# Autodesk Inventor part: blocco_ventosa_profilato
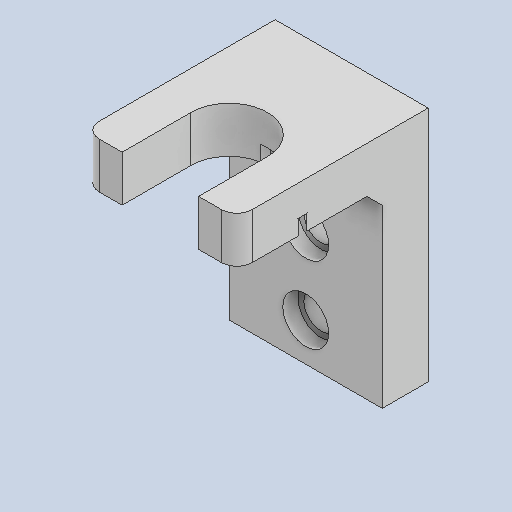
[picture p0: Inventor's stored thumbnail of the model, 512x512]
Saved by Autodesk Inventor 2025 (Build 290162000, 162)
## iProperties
Created: 2026-03
Part Number: blocco_ventosa_profilato
Material: Generico
Document SubType Name: Modeling
Designer: Ryzen5700u
Density: 1 g/cm^3
Appearance: Default
Author: Ryzen5700u
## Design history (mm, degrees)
sketch "Schizzo1"
  geometry: L1 (10, 16)-(-10, 16); L2 (-10, 16)-(-10, -16); L3 (-10, -16)-(10, -16); L4 (10, -16)-(10, 16); L5 (10, 16)-(-10, -16); L6 (-10, 16)-(10, -16); L7 (10, 0)-(-10, 0); L8 (10, 9)-(-10, 9); L9 (5, 0)-(5, 9); L10 (-5, 0)-(-5, 9); A1 r 5 centre (0, 0) between (5, 0) and (-5, 0); 4 further points
  constraints: 20 end point, 6 point on line, 5 midpoint, 4 perpendicular, 2 parallel, 2 point on circle, 1 centre point, 1 coincident, 1 horizontal, 1 tangent
  dimensions: "d0" = 10 diameter of A1; "d1" = 20 distance of L3.end L2.end; "d2" = 32 distance of L2.end L1.end; "d17" = 9 distance from line of point (0, 0) L8
extrude "Estrusione1" new body sketch "Schizzo1" distance "d3" = 6; taper "d4" = 0 deg
sketch "Schizzo2"
  geometry: L1 (-10, 16)-(10, 16); L2 (10, 16)-(10, 11); L3 (10, 11)-(-10, 11); L4 (-10, 11)-(-10, 16); 8 further points
  constraints: 8 end point, 2 parallel, 1 horizontal, 1 perpendicular, 3 other
  dimensions: "d5" = 5 distance of L1.end L2.end
extrude "Estrusione2" join sketch "Schizzo2" distance "d6" = 15; taper "d7" = 0 deg
sketch "Schizzo3"
  geometry: L1 (0, 15)-(20, 15) reference; L2 (3, 0)-(14, 0) reference; L3 (10, 15)-(10, -6); 4 further points
  constraints: 2 end point, 2 point on line, 1 midpoint, 1 perpendicular
  dimensions: "d8" = 16 distance from line of L1 point (10, -1); "d9" = 12 distance of point (10, -1) point (10, -13)
hole "Foro1" sketch "Schizzo3" at (10, -1), (10, -13) diameter "d10" = 3.4; stored, may be unused: countersink angle "d14" = 90 deg, drill point angle "d16" = 118 deg; dims "d11" = 6, "d12" = 6.5, "d13" = 3.4, "d15" = 8
fillet "Raccordo1" dims "d18" = 2
sketch "Schizzo4"
  geometry: L1 (0, 0)-(20, 0) reference; L2 (10, 0)-(10, -2); C1 r 0.5 at (10, -2); 3 further points
  constraints: 2 end point, 1 centre point, 1 coincident, 1 midpoint, 1 vertical
  dimensions: "d22" = 2 distance of L2.start L2.end; "d23" = 1 diameter of C1
extrude "Estrusione3" cut sketch "Schizzo4" distance "d24" = 30; taper "d25" = 0 deg
fillet "Raccordo3" dims "d27" = 2
sketch "Schizzo6"
  geometry: L1 (6.661, 6.392)-(-0.268, 6.392) reference; L2 (-0.268, 6.392)-(-3.732, 0.392) reference; L3 (-3.732, 0.392)-(-0.268, -5.608) reference; L4 (-0.268, -5.608)-(6.661, -5.608) reference; L5 (6.661, -5.608)-(10.125, 0.392) reference; L6 (10.125, 0.392)-(6.661, 6.392) reference; L7 (-0.354, -5.758)-(-3.905, 0.392); L8 (-3.905, 0.392)-(-0.354, 6.542); L9 (-0.354, 6.542)-(6.747, 6.542); L10 (6.747, 6.542)-(10.298, 0.392); L11 (10.298, 0.392)-(6.747, -5.758); L12 (6.747, -5.758)-(-0.354, -5.758); C1 r 4 at (3.197, 0.392) reference; 1 further point
  constraints: 12 end point, 5 other
  dimensions: "d39" = 0.15 distance between parallel lines of L3 L7
extrude "Estrusione4" cut sketch "Schizzo6" distance "d40" = 2; taper "d41" = 0 deg
sketch "Schizzo7"
  geometry: L1 (-10, -16)-(-10, 7) reference; L2 (10, 7)-(10, -16) reference; L3 (-10, -16)-(10, -16); L4 (10, -16)-(10, -10); L5 (10, -10)-(-10, -10); L6 (-10, -10)-(-10, -16); 3 further points
  constraints: 8 end point, 2 parallel, 1 horizontal, 1 perpendicular, 1 point on line
  dimensions: "d42" = 6 distance of L4.end L3.end
extrude "Estrusione5" join sketch "Schizzo7" distance "d43" = 25; taper "d44" = 0 deg
chamfer "Smusso2" distance "d45" = 2; stored, may be unused: second distance "d46" = 2, angle "d47" = 45 deg
sketch "Schizzo8"
  geometry: L1 (20, 0)-(0, 0) reference; 4 further points
  constraints: 1 midpoint
  dimensions: "d48" = 10 distance of point (10, 5) point (10, 15); "d49" = 5 distance of point (10, 0) point (10, 5)
hole "Foro3" sketch "Schizzo8" at (10, 15), (10, 5) diameter "d50" = 4.5; stored, may be unused: countersink angle "d54" = 90 deg, drill point angle "d56" = 118 deg; dims "d51" = 6, "d52" = 6, "d53" = 2, "d55" = 25
node "Solido1"
node "Riferimento1"
